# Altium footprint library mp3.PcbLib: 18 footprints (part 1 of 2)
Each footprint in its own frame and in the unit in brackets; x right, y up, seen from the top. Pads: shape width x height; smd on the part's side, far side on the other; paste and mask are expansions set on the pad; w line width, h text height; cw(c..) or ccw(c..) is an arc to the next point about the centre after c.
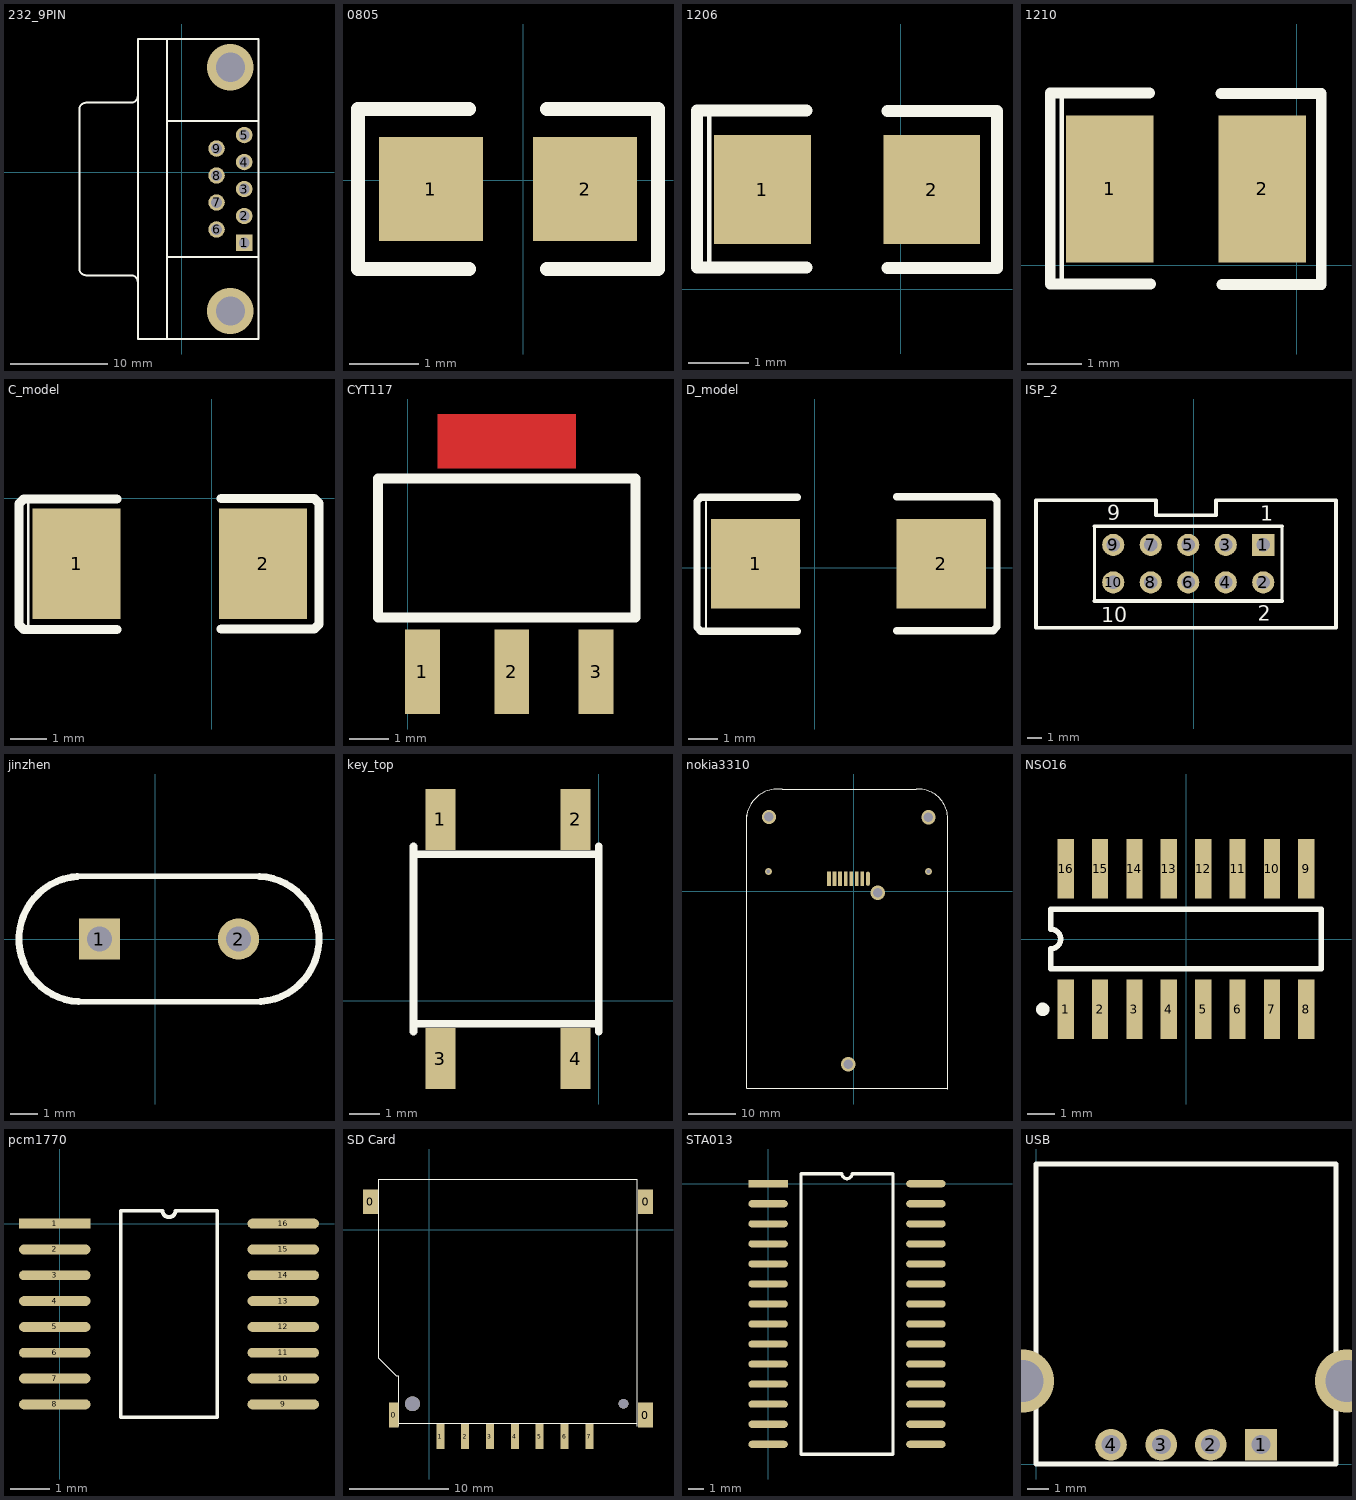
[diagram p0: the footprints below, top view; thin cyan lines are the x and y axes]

## 232_9PIN [mm]
pads (9):
  rect 1.69x1.69 hole 1.09: 1(6.399,-7.267)
  round 1.69 hole 1.09: 2(6.399,-4.497) 3(6.399,-1.727) 4(6.399,1.043) 5(6.399,3.813) 6(3.559,-5.882) 7(3.559,-3.112) 8(3.559,-0.342) 9(3.559,2.428)
via 4.979,10.768 diameter 4.76 hole 3
via 4.979,-14.251 diameter 4.76 hole 3
Top Overlay:
  lines w0.2: -9.826,-10.587 cw(c-9.826,-9.892) -10.521,-9.892 -10.521,6.438 cw(c-9.826,6.438) -9.826,7.133 ; -9.821,-10.592 -5.221,-10.592 cw(c-5.221,-11.287) -4.526,-11.287 ; -9.821,7.138 -5.221,7.138 ccw(c-5.221,7.833) -4.526,7.833 ; -1.521,-17.127 -1.521,13.673 ; -1.521,-8.727 7.879,-8.727 ; -1.521,5.273 7.879,5.273 ; -4.521,-17.127 -4.521,13.673 7.879,13.673 7.879,-17.127 -4.521,-17.127

## 0805 [mil]
pads (2):
  rect 59x59 smd: 1(-52.4,-5) 2(35,-5)
Top Overlay:
  lines w7.87: -30.75,-50.28 -93.74,-50.28 -93.74,40.28 -30.75,40.28 ; 13.35,-50.28 76.34,-50.28 76.34,40.28 13.35,40.28

## 1206 [mm]
pads (2):
  rect 1.6x1.8 smd: 1(-2.289,1.651) 2(0.511,1.651)
Top Overlay:
  lines w0.076: -3.17,0.372 -3.17,2.972
  lines w0.2: -1.557,0.362 -3.372,0.362 -3.372,2.962 -1.557,2.962 ; -0.224,0.351 1.591,0.351 1.591,2.951 -0.224,2.951

## 1210 [mm]
pads (2):
  rect 1.6x2.7 smd: 1(-3.432,1.397) 2(-0.632,1.397)
Top Overlay:
  lines w0.076: -4.31,-0.36 -4.31,3.14
  lines w0.2: -2.699,3.153 -4.52,3.153 -4.52,-0.347 -2.685,-0.347 ; -1.387,3.147 0.448,3.147 0.448,-0.353 -1.373,-0.353

## C_model [mm]
pads (2):
  rect 2.4x3 smd: 1(-3.683,-1.778) 2(1.397,-1.778)
Top Overlay:
  lines w0.076: -5.001,-3.443 -5.001,-0.141
  lines w0.254: -2.584,-3.57 -4.87,-3.57 -5.124,-3.57 -5.251,-3.443 -5.251,-0.141 -5.124,-0.014 -4.87,-0.014 -2.584,-0.014 ; 0.254,-3.556 2.54,-3.556 2.794,-3.556 2.921,-3.429 2.921,-0.127 2.794,0 2.54,0 0.254,0

## CYT117 [mil]
pads (3):
  rect 35x85 smd: 1(15,-495) 2(105,-495) 3(190,-495)
Top Layer:
  rectangle: 30,-290 170,-235
Top Overlay:
  lines w10: -30,-440 -30,-300 230,-300 230,-440 -30,-440

## D_model [mil]
pads (2):
  rect 120x120 smd: 1(-80,5) 2(170,5)
Top Overlay:
  lines w3: -146.57,-82.13 -146.57,87.87
  lines w10: -23.78,-85.55 -133.78,-85.55 -138.78,-85.55 -153.78,-85.55 -158.78,-80.55 -158.78,89.45 -153.78,94.45 -23.78,94.45 ; 110,-85 240,-85 245,-80 245,90 240,95 225,95 220,95 110,95

## ISP_2 [mm]
pads (10):
  rect 1.5x1.5 hole 0.9: 1(4.724,-10.262)
  round 1.5 hole 0.9: 2(4.724,-12.802) 3(2.184,-10.262) 4(2.184,-12.802) 5(-0.356,-10.262) 6(-0.356,-12.802) 7(-2.896,-10.262) 8(-2.896,-12.802) 9(-5.436,-10.262) 10(-5.436,-12.802)
Top Overlay:
  lines w0.2: -6.706,-14.072 -6.706,-8.992 ; 5.994,-14.072 5.994,-8.992
  lines w0.254: -6.706,-14.072 5.994,-14.072 ; -6.706,-8.992 5.994,-8.992 ; -10.668,-15.875 9.652,-15.875 9.652,-7.239 1.524,-7.239 1.524,-8.255 -2.54,-8.255 -2.54,-7.239 -10.668,-7.239 -10.668,-15.875
  text "10" at -6.248,-15.494 h1.02
  text "9" at -5.842,-8.585 h1.02
  text "2" at 4.369,-15.392 h1.02
  text "1" at 4.521,-8.636 h1.02

## jinzhen [mm]
pads (2):
  rect 1.5x1.5 hole 0.9: 1(-2.032,0)
  round 1.5 hole 0.9: 2(3.048,0)
Top Overlay:
  lines w0.2: -3.048,2.286 3.81,2.286 ; -2.794,-2.286 3.859,-2.284
  lines w0.254: -2.843,2.284 ccw(c-2.68,0.001) -2.794,-2.286 ; 3.81,2.286 cw(c3.696,-0.001) 3.859,-2.284

## key_top [mm]
pads (4):
  rect 1x2 smd: 1(-5.207,5.969) 2(-0.762,5.969) 3(-5.207,-1.905) 4(-0.762,-1.905)
Top Overlay:
  lines w0.254: -6.096,-1.016 -6.096,5.08 ; -6.096,-0.762 0,-0.762 ; -6.096,4.826 0,4.826 ; 0,-1.016 0,5.08

## nokia3310 [mm]
pads (8):
  oval 0.8x3 smd: 1(2.972,2.702)
  rect 0.8x3 smd: 2(1.792,2.702) 3(0.612,2.702) 4(-0.568,2.702) 5(-1.748,2.702) 6(-2.928,2.702) 7(-4.108,2.702) 8(-5.288,2.702)
via -18.115,4.226 diameter 1.524 hole 0.762
via 15.794,4.226 diameter 1.524 hole 0.762
via -17.994,15.792 diameter 3 hole 2
via 15.782,15.722 diameter 3 hole 2
via 5.064,-0.27 diameter 3 hole 2
via -1.181,-36.598 diameter 3 hole 2
Top Overlay:
  lines w0.254: -22.741,15.97 cw(c-16.148,15.044) -15.222,21.636 13.18,21.636 cw(c13.674,15.449) 19.861,15.942 ; -22.697,16.102 -22.697,-41.682 19.735,-41.682 ; 19.885,-41.832 19.885,15.952

## NSO16 [mm]
height 1.75
pads (16):
  rect 0.6x2.2 smd: 1(-4.445,-2.6) 2(-3.175,-2.6) 3(-1.905,-2.6) 4(-0.635,-2.6) 5(0.635,-2.6) 6(1.905,-2.6) 7(3.175,-2.6) 8(4.445,-2.6) 9(4.445,2.6) 10(3.175,2.6) 11(1.905,2.6) 12(0.635,2.6) 13(-0.635,2.6) 14(-1.905,2.6) 15(-3.175,2.6) 16(-4.445,2.6)
Top Overlay:
  circle w0.25: c-5.295,-2.6 r0.125
  lines w0.2: -5,-1.1 5,-1.1 5,1.1 -5,1.1 -5,0.367 cw(c-5,0) -5,-0.367 -5,-1.1

## pcm1770 [mm]
pads (16):
  rect 1.8x0.25 smd: 1(-0.127,0)
  oval 1.8x0.25 smd: 2(-0.127,-0.65) 3(-0.127,-1.3) 4(-0.127,-1.95) 5(-0.127,-2.6) 6(-0.127,-3.25) 7(-0.127,-3.9) 8(-0.127,-4.55) 9(5.627,-4.55) 10(5.627,-3.9) 11(5.627,-3.25) 12(5.627,-2.6) 13(5.627,-1.95) 14(5.627,-1.3) 15(5.627,-0.65) 16(5.627,0)
Top Overlay:
  lines w0.1: 1.535,-4.875 3.965,-4.875 3.965,0.325 2.912,0.325 cw(c2.75,0.325) 2.588,0.325 1.535,0.325 1.535,-4.875

## SD Card [mm]
pads (11):
  rect 1.5x2.5 smd: 0(-5.9,2.794) 0(21.77,-18.669) 0(21.78,2.794)
  rect 1x2.5 smd: 0(-3.556,-18.669)
  rect 0.8x2.5 smd: 1(1.129,-20.828) 2(3.629,-20.828) 3(6.129,-20.828) 4(8.629,-20.828) 5(11.129,-20.828) 6(13.629,-20.828) 7(16.129,-20.828)
via 19.558,-17.526 diameter 1 hole 1
via -1.651,-17.526 diameter 1.5 hole 1.5
Top Overlay:
  lines w0.1: -3.047,-19.812 -3.047,-14.733 -3.301,-14.733 -5.08,-12.954 -5.08,5.08 20.955,5.08 20.955,-19.812 ; -3.047,-19.512 20.955,-19.512

## STA013 [mm]
pads (28):
  rect 2.5x0.45 smd: 1(0,0)
  oval 2.5x0.45 smd: 2(0,-1.27) 3(0,-2.54) 4(0,-3.81) 5(0,-5.08) 6(0,-6.35) 7(0,-7.62) 8(0,-8.89) 9(0,-10.16) 10(0,-11.43) 11(0,-12.7) 12(0,-13.97) 13(0,-15.24) 14(0,-16.51) 15(10,-16.51) 16(10,-15.24) 17(10,-13.97) 18(10,-12.7) 19(10,-11.43) 20(10,-10.16) 21(10,-8.89) 22(10,-7.62) 23(10,-6.35) 24(10,-5.08) 25(10,-3.81) 26(10,-2.54) 27(10,-1.27) 28(10,0)
Top Overlay:
  lines w0.2: 2.085,-17.145 2.085,0.635 4.683,0.635 ccw(c5,0.635) 5.318,0.635 7.915,0.635 7.915,-17.145 2.085,-17.145

## USB [mm]
pads (4):
  rect 1.5x1.5 hole 0.9: 1(10.668,0.914)
  round 1.5 hole 0.9: 2(8.28,0.914) 3(5.944,0.914) 4(3.556,0.914)
via -0.635,3.937 diameter 3 hole 2
via 14.732,3.937 diameter 3 hole 2
Top Overlay:
  lines w0.254: 0,0 0,14.224 14.224,14.224 14.224,0 0,0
